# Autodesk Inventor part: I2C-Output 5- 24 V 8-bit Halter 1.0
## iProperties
Created: 2016-11
Part Number: I2C-Output 5- 24 V 8-bit Halter 1.0
Material: Standard
Document SubType Name: Blech
Designer: Acer
Density: 1 g/cm^3
Sheet Metal Rule: Standard_mm
Author: Acer
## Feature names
1. Extrusion1
2. Extrusion3
3. Extrusion5
4. Extrusion6
5. Rundung2 [Fillet]
6. Rundung3 [Fillet]
7. Extrusion8
